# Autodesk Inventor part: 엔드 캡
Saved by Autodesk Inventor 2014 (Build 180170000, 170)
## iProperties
Created: 2026-04
Part Number: 엔드 캡
Material: 강철, 연강
Document SubType Name: Modeling
Designer: dg
Density: 7.86 g/cm^3
Appearance: 강철
Mass: 15.3024 g
Surface Area: 17.4653 cm^2
Volume: 1.94687 cm^3
Author: jhkim
Creation Date: 2026-03-27
Sending System: Autodesk Inventor 2026
Preprocessor: ST-DEVELOPER v20.1
Author: dg
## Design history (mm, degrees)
node "엔드 캡1"
node "솔리드1"
node "기준1"
